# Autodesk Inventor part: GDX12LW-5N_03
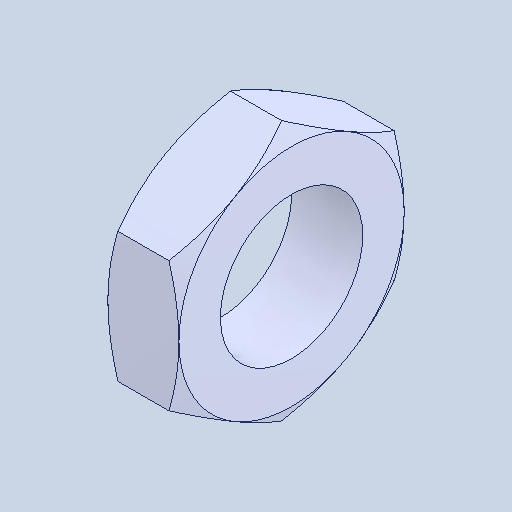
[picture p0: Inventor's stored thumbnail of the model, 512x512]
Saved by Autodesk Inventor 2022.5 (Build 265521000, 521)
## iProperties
Created: 2024-06
Part Number: GDX12LW-5N_03
Material: 一般
Document SubType Name: Modeling
Designer: ImaoCorp
Density: 1 g/cm^3
Appearance: 既定
Author: ImaoCorp
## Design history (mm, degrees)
feature "GDX12LW-5N_03"
node "ソリッド1"
